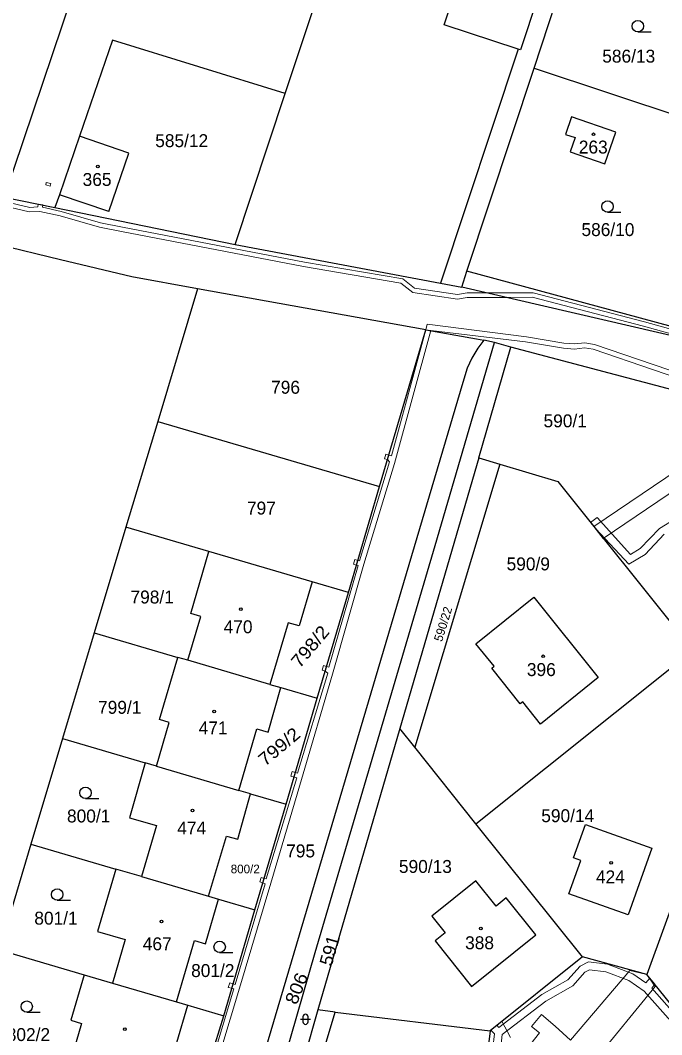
# Model space of a CAD drawing. Extents: x -701211 to -698780, y -1014269 to -1012378.
# Drawn here: x -700673.2 to -700589, y -1013402.8 to -1013269.6 of the extents above; entities that cross this region are included whole.
import ezdxf
from ezdxf.enums import TextEntityAlignment as Align

# ---------------------------------------------------------------- set-up
doc = ezdxf.new("R2010")
doc.units = 0
doc.header["$LTSCALE"] = 0.68
for name, color, linetype, lineweight in [('1', 7, 'Continuous', 25), ('13', 7, 'Continuous', 13), ('3', 7, 'Continuous', 25), ('5', 7, 'Continuous', 25)]:
    doc.layers.add(name, color=color, linetype=linetype, lineweight=lineweight)
doc.layers.add('2', color=7, linetype='Continuous')

msp = doc.modelspace()

# ---------------------------------------------------------------- linework, layer by layer
at = {"layer": '1'}
for p, q in [((-700654.49, -1013230.98), (-700675.3, -1013292.82)), ((-700638.4, -1013279.21), (-700625.56, -1013240.47)), ((-700599.64, -1013249.62), (-700607.52, -1013273.5)), ((-700617.54, -1013270.22), (-700613.88, -1013259.13)), ((-700607.82, -1013273.4), (-700617.54, -1013270.22)), ((-700661.08, -1013272.23), (-700665.42, -1013284.82)), ((-700607.82, -1013273.4), (-700617.99, -1013304.12)), ((-700607.52, -1013273.5), (-700607.82, -1013273.4)), ((-700605.71, -1013275.89), (-700569.99, -1013287.76)), ((-700600.8, -1013282.3), (-700601.58, -1013284.6)), ((-700594.99, -1013284.29), (-700600.8, -1013282.3)), ((-700601.58, -1013284.6), (-700600.35, -1013285.02)), ((-700596.42, -1013288.46), (-700594.99, -1013284.29)), ((-700665.42, -1013284.82), (-700668.06, -1013292.51)), ((-700658.94, -1013287.05), (-700665.42, -1013284.82)), ((-700600.35, -1013285.02), (-700600.99, -1013286.9)), ((-700661.58, -1013294.74), (-700658.94, -1013287.05)), ((-700600.99, -1013286.9), (-700596.42, -1013288.46)), ((-700668.06, -1013292.51), (-700668.64, -1013294.19)), ((-700661.58, -1013294.74), (-700668.06, -1013292.51)), ((-700675.3, -1013292.82), (-700668.64, -1013294.19)), ((-700668.64, -1013294.19), (-700644.98, -1013299.07)), ((-700667.89, -1013301.06), (-700684.79, -1013296.99)), ((-700644.98, -1013299.07), (-700617.99, -1013304.12)), ((-700658.55, -1013303.3), (-700667.89, -1013301.06)), ((-700649.92, -1013304.89), (-700658.55, -1013303.3)), ((-700578.24, -1013312.37), (-700614.54, -1013302.57)), ((-700617.99, -1013304.12), (-700615.23, -1013304.64)), ((-700570.79, -1013314.98), (-700615.23, -1013304.64)), ((-700649.92, -1013304.89), (-700655.14, -1013322.29)), ((-700619.95, -1013310.25), (-700649.92, -1013304.89)), ((-700618.73, -1013338.57), (-700610.91, -1013311.93)), ((-700613.13, -1013312.67), (-700613.9, -1013313.98)), ((-700613.29, -1013311.44), (-700612.31, -1013311.64)), ((-700612.31, -1013311.64), (-700613.13, -1013312.67)), ((-700612.98, -1013327.07), (-700608.77, -1013312.52)), ((-700610.91, -1013311.93), (-700612.31, -1013311.64)), ((-700608.77, -1013312.52), (-700610.91, -1013311.93)), ((-700578.63, -1013320.51), (-700608.77, -1013312.52)), ((-700613.9, -1013313.98), (-700614.49, -1013315.31)), ((-700614.49, -1013315.31), (-700615.1, -1013317.2)), ((-700615.1, -1013317.2), (-700658.4, -1013463.4)), ((-700655.14, -1013322.29), (-700659.31, -1013336.19)), ((-700612.98, -1013327.07), (-700623.37, -1013362.62)), ((-700612.98, -1013327.07), (-700610.23, -1013327.9)), ((-700610.23, -1013327.9), (-700621.39, -1013365.09)), ((-700610.23, -1013327.9), (-700602.61, -1013330.19)), ((-700630.11, -1013344.77), (-700626.02, -1013330.85)), ((-700602.61, -1013330.19), (-700584.87, -1013352.36)), ((-700659.31, -1013336.19), (-700663.47, -1013350.05)), ((-700648.41, -1013339.39), (-700659.31, -1013336.19)), ((-700634.46, -1013392.05), (-700618.73, -1013338.57)), ((-700634.86, -1013343.37), (-700648.41, -1013339.39)), ((-700630.11, -1013344.77), (-700634.86, -1013343.37)), ((-700634.2, -1013358.66), (-700630.11, -1013344.77)), ((-700613.36, -1013351.49), (-700605.74, -1013345.38)), ((-700605.74, -1013345.38), (-700597.29, -1013355.92)), ((-700663.47, -1013350.05), (-700667.63, -1013363.93)), ((-700663.47, -1013350.05), (-700652.48, -1013353.28)), ((-700610.97, -1013354.45), (-700613.36, -1013351.49)), ((-700613.35, -1013375.15), (-700584.87, -1013352.36)), ((-700651.2, -1013353.66), (-700652.48, -1013353.28)), ((-700640.42, -1013356.83), (-700651.2, -1013353.66)), ((-700611.29, -1013354.7), (-700610.97, -1013354.45)), ((-700607.53, -1013359.37), (-700611.29, -1013354.7)), ((-700597.29, -1013355.92), (-700604.87, -1013362.05)), ((-700638.29, -1013372.58), (-700634.2, -1013358.66)), ((-700607.22, -1013359.12), (-700607.53, -1013359.37)), ((-700604.87, -1013362.05), (-700607.22, -1013359.12)), ((-700578.44, -1013360.4), (-700590.9, -1013394.94)), ((-700623.37, -1013362.62), (-700634.11, -1013399.59)), ((-700621.39, -1013365.09), (-700623.37, -1013362.62)), ((-700667.63, -1013363.93), (-700671.79, -1013377.81)), ((-700667.63, -1013363.93), (-700656.8, -1013367.12)), ((-700613.35, -1013375.15), (-700621.39, -1013365.09)), ((-700656.8, -1013367.12), (-700658.84, -1013374.34)), ((-700655.31, -1013367.56), (-700656.8, -1013367.12)), ((-700655.31, -1013367.56), (-700644.51, -1013370.75)), ((-700644.64, -1013377.15), (-700642.97, -1013371.2)), ((-700642.97, -1013371.2), (-700644.51, -1013370.75)), ((-700642.97, -1013371.2), (-700638.29, -1013372.58)), ((-700642.37, -1013386.46), (-700638.29, -1013372.58)), ((-700658.84, -1013374.34), (-700655.3, -1013375.36)), ((-700599.37, -1013392.61), (-700613.35, -1013375.15)), ((-700600.56, -1013379.59), (-700598.99, -1013375.22)), ((-700598.99, -1013375.22), (-700590.25, -1013378.35)), ((-700671.79, -1013377.81), (-700675.96, -1013391.69)), ((-700671.79, -1013377.81), (-700660.62, -1013381.09)), ((-700648.46, -1013384.66), (-700646.12, -1013376.75)), ((-700646.12, -1013376.75), (-700644.64, -1013377.15)), ((-700590.25, -1013378.35), (-700593.38, -1013387.1)), ((-700601.14, -1013384.32), (-700599.58, -1013379.95)), ((-700599.58, -1013379.95), (-700600.56, -1013379.59)), ((-700660.62, -1013381.09), (-700663.05, -1013389.27)), ((-700657.29, -1013382.07), (-700660.62, -1013381.09)), ((-700613.39, -1013382.64), (-700619.17, -1013387.26)), ((-700610.72, -1013385.95), (-700613.39, -1013382.64)), ((-700648.46, -1013384.66), (-700647.15, -1013385.05)), ((-700593.38, -1013387.1), (-700601.14, -1013384.32)), ((-700648.88, -1013390.89), (-700647.15, -1013385.05)), ((-700647.15, -1013385.05), (-700642.37, -1013386.46)), ((-700609.38, -1013384.88), (-700610.72, -1013385.95)), ((-700605.51, -1013389.73), (-700609.38, -1013384.88)), ((-700646.46, -1013400.36), (-700642.37, -1013386.46)), ((-700619.17, -1013387.26), (-700617.41, -1013389.44)), ((-700663.05, -1013389.27), (-700659.42, -1013390.34)), ((-700617.41, -1013389.44), (-700618.73, -1013390.51)), ((-700613.94, -1013396.52), (-700605.51, -1013389.73)), ((-700659.42, -1013390.34), (-700661.08, -1013396.06)), ((-700652.69, -1013398.53), (-700650.31, -1013390.45)), ((-700650.31, -1013390.45), (-700648.88, -1013390.89)), ((-700618.73, -1013390.51), (-700613.94, -1013396.52)), ((-700675.96, -1013391.69), (-700664.78, -1013394.98)), ((-700640.66, -1013413.61), (-700634.46, -1013392.05)), ((-700590.9, -1013394.94), (-700599.37, -1013392.61)), ((-700664.78, -1013394.98), (-700661.08, -1013396.06)), ((-700581.46, -1013406.73), (-700590.9, -1013394.94)), ((-700661.08, -1013396.06), (-700652.69, -1013398.53)), ((-700652.69, -1013398.53), (-700651.18, -1013398.97)), ((-700652.62, -1013403.88), (-700651.18, -1013398.97)), ((-700651.18, -1013398.97), (-700646.46, -1013400.36)), ((-700650.74, -1013414.21), (-700646.46, -1013400.36)), ((-700634.11, -1013399.59), (-700642.67, -1013429.18)), ((-700640.42, -1013428.47), (-700631.83, -1013399.87)), ((-700631.83, -1013399.87), (-700634.11, -1013399.59)), ((-700631.83, -1013399.87), (-700611.51, -1013402.32)), ((-700665.13, -1013401.38), (-700667.51, -1013409.28))]:
    msp.add_line(p, q, dxfattribs=at)
for points in [[(-700605.71, -1013275.89), (-700600.93, -1013261.31), (-700565.16, -1013273.2)], [(-700644.98, -1013299.07), (-700638.4, -1013279.21), (-700661.08, -1013272.23)], [(-700615.23, -1013304.64), (-700614.54, -1013302.57), (-700605.71, -1013275.89)], [(-700655.14, -1013322.29), (-700626.02, -1013330.85), (-700619.95, -1013310.25), (-700613.29, -1013311.44)], [(-700651.2, -1013353.66), (-700649.49, -1013347.91), (-700650.79, -1013347.53), (-700648.41, -1013339.39)], [(-700634.86, -1013343.37), (-700636.56, -1013349.16), (-700638.02, -1013348.75), (-700640.42, -1013356.83)], [(-700655.31, -1013367.56), (-700653.62, -1013361.83), (-700654.91, -1013361.44), (-700652.48, -1013353.28)], [(-700644.51, -1013370.75), (-700642.11, -1013362.66), (-700640.65, -1013363.09), (-700638.96, -1013357.26)], [(-700640.42, -1013356.83), (-700638.96, -1013357.26), (-700634.2, -1013358.66)], [(-700655.3, -1013375.36), (-700657.29, -1013382.07), (-700648.46, -1013384.66)], [(-700599.37, -1013392.61), (-700611.51, -1013402.32), (-700613.64, -1013420.05)], [(-700664.78, -1013394.98), (-700666.56, -1013400.94), (-700665.13, -1013401.38)]]:
    msp.add_lwpolyline(points, dxfattribs=at)
at = {"layer": '13'}
for points in [[(-700669.18, -1013291.03), (-700669.77, -1013290.89), (-700669.85, -1013291.23), (-700669.26, -1013291.37)], [(-700574.37, -1013317.63), (-700575.44, -1013320.9), (-700575.88, -1013321.2), (-700597.88, -1013336.1), (-700596.63, -1013337.67), (-700573.76, -1013322.18), (-700573.63, -1013321.77), (-700572.47, -1013318.25)], [(-700645.4, -1013396.75), (-700645.23, -1013396.17), (-700645.69, -1013396.03), (-700645.87, -1013396.62)]]:
    msp.add_lwpolyline(points, close=True, dxfattribs=at)
for points in [[(-700681.16, -1013292.63), (-700672, -1013294.78), (-700670.62, -1013294.71), (-700667.96, -1013295.29), (-700662.8, -1013296.79), (-700659.89, -1013297.36), (-700635.99, -1013301.95), (-700623.23, -1013304.15), (-700621.66, -1013305.34), (-700615.77, -1013306.23), (-700614.5, -1013306.02), (-700609.38, -1013306), (-700605.98, -1013305.99), (-700591.37, -1013309.79), (-700582.22, -1013312.32)], [(-700580.37, -1013312.21), (-700591.21, -1013309.21), (-700605.83, -1013305.41), (-700611.95, -1013305.4), (-700614.49, -1013305.4), (-700615.78, -1013305.63), (-700621.42, -1013304.78), (-700622.97, -1013303.58), (-700635.87, -1013301.36), (-700659.77, -1013296.77), (-700662.66, -1013296.2), (-700667.81, -1013294.7), (-700670.27, -1013294.17), (-700670.24, -1013293.86), (-700670.83, -1013293.74), (-700670.87, -1013294.12), (-700671.94, -1013294.18), (-700681.02, -1013292.04)], [(-700582.24, -1013317.47), (-700597.81, -1013312.18), (-700599.07, -1013311.98), (-700600.42, -1013312.12), (-700601.8, -1013312.03), (-700606.73, -1013311.19), (-700619.74, -1013309.52), (-700619.95, -1013310.25), (-700619.26, -1013310.37), (-700606.83, -1013311.85), (-700601.88, -1013312.69), (-700600.4, -1013312.78), (-700599.09, -1013312.64), (-700597.97, -1013312.82), (-700582.12, -1013318.21)], [(-700648.76, -1013411.25), (-700644.54, -1013397.15), (-700640.3, -1013382.93), (-700636.26, -1013369.33), (-700632.18, -1013355.48), (-700628.09, -1013341.05), (-700624.05, -1013327.81), (-700619.26, -1013310.37), (-700619.95, -1013310.25), (-700624.45, -1013326.83), (-700624.8, -1013326.72), (-700625.19, -1013326.6), (-700625.37, -1013327.19), (-700624.98, -1013327.31), (-700624.69, -1013327.61), (-700628.65, -1013340.62), (-700628.87, -1013340.55), (-700629.25, -1013340.44), (-700629.43, -1013341.05), (-700629.05, -1013341.17), (-700628.84, -1013341.22), (-700632.68, -1013354.55), (-700632.97, -1013354.47), (-700633.38, -1013354.36), (-700633.55, -1013354.96), (-700633.15, -1013355.08), (-700632.82, -1013355.36), (-700636.8, -1013368.49), (-700637.07, -1013368.42), (-700637.5, -1013368.29), (-700637.67, -1013368.88), (-700637.24, -1013369.02), (-700636.89, -1013369.12), (-700640.9, -1013382.38), (-700641.15, -1013382.31), (-700641.58, -1013382.18), (-700641.75, -1013382.77), (-700641.33, -1013382.91), (-700641.02, -1013383.02), (-700644.99, -1013396.24), (-700645.23, -1013396.17), (-700645.4, -1013396.75), (-700645.13, -1013396.83), (-700649.13, -1013410.08)], [(-700587.13, -1013335.03), (-700589.27, -1013336.34), (-700591.78, -1013338.98), (-700593.08, -1013339.76), (-700597.42, -1013334.93), (-700598.31, -1013335.57), (-700597.88, -1013336.1), (-700597.63, -1013336.41), (-700593.28, -1013341.04), (-700591.14, -1013339.76), (-700588.63, -1013337.12)], [(-700582.92, -1013406.24), (-700586.98, -1013400.44), (-700590.28, -1013396.71), (-700589.88, -1013396.21), (-700590.52, -1013395.41), (-700591.03, -1013396.04), (-700592.77, -1013394.83), (-700596.08, -1013393.59), (-700598.59, -1013393.26), (-700599.66, -1013393.82), (-700601.27, -1013395.63), (-700604.72, -1013397.58), (-700610.34, -1013401.88), (-700610.61, -1013401.6), (-700611.4, -1013402.24), (-700610.91, -1013402.73), (-700611.13, -1013404.55)], [(-700609.92, -1013402.81), (-700604.16, -1013398.42), (-700600.63, -1013396.41), (-700599.04, -1013394.62), (-700598.43, -1013394.3), (-700596.32, -1013394.57), (-700593.27, -1013395.73), (-700591.26, -1013397.11), (-700587.76, -1013401.06), (-700583.99, -1013406.51)], [(-700597.84, -1013406.33), (-700589.81, -1013396.52), (-700590.9, -1013394.94), (-700593.14, -1013394.39), (-700600.92, -1013403.58), (-700602.94, -1013401.7), (-700604.77, -1013400.2), (-700606.04, -1013401.75), (-700605, -1013402.6), (-700607.1, -1013405.26)], [(-700608.84, -1013403.19), (-700609.95, -1013401.07), (-700611.51, -1013402.32), (-700611.77, -1013404.49)], [(-700610.11, -1013404.49), (-700609.92, -1013402.81)]]:
    msp.add_lwpolyline(points, dxfattribs=at)
at = {"layer": '3'}
for p, q in [((-700592.093, -1013271.12), (-700590.343, -1013271.12)), ((-700596.073, -1013294.82), (-700594.323, -1013294.82)), ((-700664.623, -1013371.82), (-700662.873, -1013371.82)), ((-700668.333, -1013385.18), (-700666.583, -1013385.18)), ((-700647.013, -1013392.06), (-700645.263, -1013392.06)), ((-700672.343, -1013399.9), (-700670.593, -1013399.9)), ((-700636.075, -1013400.475), (-700636.075, -1013401.146)), ((-700635.405, -1013401.146), (-700635.405, -1013400.475)), ((-700636.411, -1013400.811), (-700635.069, -1013400.811))]:
    msp.add_line(p, q, dxfattribs=at)
for centre in [(-700592.0929, -1013270.3698), (-700596.0729, -1013294.0698), (-700664.6229, -1013371.0698), (-700668.3329, -1013384.4298), (-700647.0129, -1013391.3098), (-700672.3429, -1013399.1498)]:
    msp.add_circle(centre, 0.75, dxfattribs=at)
for centre, start, end in [((-700635.74, -1013400.4756), 0, 180), ((-700635.74, -1013401.1456), 180, 359.98789)]:
    msp.add_arc(centre, 0.335, start, end, dxfattribs=at)
at = {"layer": '5'}
for centre in [(-700597.9068, -1013284.5792), (-700663.0168, -1013288.8092), (-700644.2268, -1013346.9392), (-700604.5168, -1013353.1392), (-700647.7168, -1013360.3792), (-700650.5868, -1013373.3892), (-700595.5868, -1013380.2592), (-700654.6468, -1013387.9592), (-700612.7268, -1013388.8892), (-700659.4668, -1013402.1192)]:
    msp.add_circle(centre, 0.175, dxfattribs=at)

# ---------------------------------------------------------------- texts
at = {"layer": '2'}
for s, p in [('586/13', (-700596.77, -1013275.165)), ('585/12', (-700655.47, -1013286.265)), ('263', (-700599.85, -1013287.105)), ('365', (-700665, -1013291.365)), ('586/10', (-700599.5, -1013297.945)), ('590/1', (-700604.48, -1013323.065)), ('590/9', (-700609.33, -1013341.855)), ('396', (-700606.67, -1013355.735)), ('590/14', (-700604.78, -1013374.925)), ('590/13', (-700623.47, -1013381.595)), ('424', (-700597.6, -1013382.965)), ('388', (-700614.78, -1013391.615))]:
    msp.add_text(s, height=1.7, dxfattribs=at).set_placement(p)
for s, height, p in [('796', 1.7, (-700638.359, -1013318.655)), ('797', 1.7, (-700641.529, -1013334.525)), ('798/1', 1.7, (-700655.87, -1013346.205)), ('470', 1.7, (-700644.589, -1013350.115)), ('799/1', 1.7, (-700660.13, -1013360.695)), ('471', 1.7, (-700647.869, -1013363.395)), ('800/1', 1.7, (-700664.21, -1013374.965)), ('474', 1.7, (-700650.679, -1013376.545)), ('795', 1.7, (-700636.379, -1013379.555)), ('800/2', 1.139, (-700643.65, -1013381.644)), ('801/1', 1.7, (-700668.5, -1013388.385)), ('467', 1.7, (-700655.209, -1013391.755)), ('801/2', 1.7, (-700647.91, -1013395.265)), ('802/2', 1.7, (-700672.12, -1013403.675))]:
    msp.add_text(s, height=height, dxfattribs=at).set_placement(p, align=Align.CENTER)
msp.add_text('590/22', height=1.14, rotation=73, dxfattribs=at).set_placement((-700617.1314, -1013349.0682), align=Align.CENTER)
for s, rotation, width, p in [('798/2', 50, 1.1, (-700634.4807, -1013352.3944)), ('799/2', 40, 1.1, (-700638.6484, -1013365.6517)), ('591', 74, 1.05, (-700631.7565, -1013392.0068)), ('806', 68, 1.1, (-700636.1303, -1013397.0869))]:
    msp.add_text(s, height=1.7, rotation=rotation, dxfattribs=dict(at, width=width)).set_placement(p, align=Align.CENTER)

doc.saveas('drawing.dxf')
